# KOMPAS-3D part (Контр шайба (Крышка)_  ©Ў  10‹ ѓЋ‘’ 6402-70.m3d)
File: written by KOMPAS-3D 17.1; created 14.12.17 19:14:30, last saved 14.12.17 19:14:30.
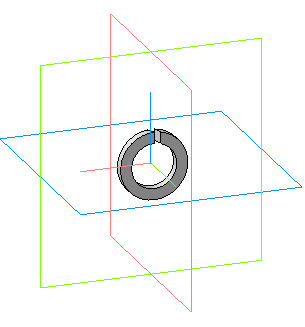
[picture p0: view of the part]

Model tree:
1. Операция без истории:1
